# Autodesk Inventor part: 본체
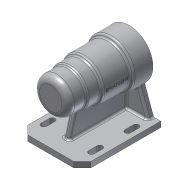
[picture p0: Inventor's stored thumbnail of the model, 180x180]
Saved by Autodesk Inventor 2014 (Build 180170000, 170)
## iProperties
Created: 2017-09
Part Number: 본체
Material: 알루미늄 6061
Document SubType Name: Modeling
Designer: user
Density: 2.71 g/cm^3
Appearance: 알루미늄 - 평지
Mass: 702.995 g
Surface Area: 713.313 cm^2
Volume: 259.408 cm^3
Author: user
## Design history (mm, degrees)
sketch "스케치1"
  geometry: L1 (0, 56)-(0, -56); L2 (0, 56)-(25, 56); L3 (25, 56)-(25, 31); L4 (25, 31)-(27, 31); L5 (27, 31)-(27, 11); L6 (27, 11)-(30, 11); L7 (30, 11)-(30, -28); L8 (30, -28)-(34, -28); L9 (34, -28)-(34, -56); L10 (34, -56)-(0, -56); 2 further points
  constraints: 20 end point, 6 parallel, 3 perpendicular, 1 coincident, 1 midpoint, 1 vertical
  dimensions: "d0" = 112 distance of L1.start L1.end; "d1" = 50 diameter of L3 L1; "d2" = 54 diameter of L5 L1; "d3" = 60 diameter of L7 L1; "d4" = 25 vertical distance of L2.end L4.end; "d5" = 45 distance between parallel lines of L6 L2; "d6" = 84 distance between parallel lines of L2 L8; "d7" = 112 distance between parallel lines of L2 L10 (derived); "d8" = 68 diameter of L9 L1
revolve "회전1" sketch "스케치1" stored, may be unused: angle "d9" = 90 deg
sketch "스케치2"
  geometry: C1 r 34 at (0, 0) reference; C2 r 21 at (0, 0)
  constraints: 1 centre point, 1 coincident
  dimensions: "d10" = 42 diameter of C2
extrude "돌출1" cut sketch "스케치2" distance "d11" = 15; taper "d12" = 0 deg
sketch "스케치3"
  geometry: C1 r 21 at (0, 0) reference; C2 r 24 at (0, 0)
  constraints: 1 centre point, 1 coincident
  dimensions: "d13" = 48 diameter of C2
extrude "돌출2" cut sketch "스케치3" distance "d14" = 54; taper "d15" = 0 deg
sketch "스케치4"
  geometry: C1 r 24 at (0, 0) reference; C2 r 21 at (0, 0)
  constraints: 1 centre point, 1 coincident
  dimensions: "d16" = 42 diameter of C2
extrude "돌출3" cut sketch "스케치4" distance "d17" = 12; taper "d18" = 0 deg
sketch "스케치5"
  geometry: C1 r 21 at (0, 0) reference; C2 r 17.5 at (0, 0)
  constraints: 1 centre point, 1 coincident
  dimensions: "d19" = 35 diameter of C2
extrude "돌출4" cut sketch "스케치5" distance "d20" = 18; taper "d21" = 0 deg
sketch "스케치6"
  geometry: C1 r 17.5 at (0, 0) reference; C2 r 16 at (0, 0)
  constraints: 1 centre point, 1 coincident
  dimensions: "d22" = 32 diameter of C2
extrude "돌출5" cut sketch "스케치6" distance "d23" = 4; taper "d24" = 0 deg
sketch "스케치7"
  geometry: C1 r 16 at (0, 0) reference; C2 r 10.5 at (0, 0)
  constraints: 1 centre point, 1 coincident
  dimensions: "d25" = 21 diameter of C2
extrude "돌출6" cut sketch "스케치7" distance "d26" = 3; taper "d27" = 0 deg
node "작업 평면1"
sketch "스케치8"
  geometry: L1 (-45, 56)-(45, 56); L2 (45, 56)-(45, -56); L3 (45, -56)-(-45, -56); L4 (-45, -56)-(-45, 56); L5 (-45, 56)-(45, -56); L6 (-45, -56)-(45, 56); 2 further points
  constraints: 12 end point, 2 parallel, 1 coincident, 1 horizontal, 1 midpoint, 1 perpendicular
  dimensions: "d29" = 90 distance of L2.end L3.end; "d30" = 112 distance of L1.end L2.end
extrude "돌출7" join sketch "스케치8" distance "d31" = 8; taper "d32" = 0 deg
sketch "스케치9"
  geometry: L1 (45, -62)-(-45, -62) reference; L2 (-21.9, -26.008)-(-35, -62); L3 (21.9, -26.008)-(35, -62); L4 (0, 0)-(0, -34); L5 (-35, -62)-(35, -62); A1 r 34 centre (0, 0) between (-21.9, -26.008) and (21.9, -26.008) reference; A2 r 34 centre (0, 0) between (-21.9, -26.008) and (21.9, -26.008)
  constraints: 8 end point, 6 point on circle, 2 point on line, 1 centre point, 1 collinear, 1 perpendicular
  dimensions: "d33" = 110 deg angle of L1 L3; "d34" = 110 deg angle of L1 L2; "d35" = 10 distance of L1.end L2.end; "d36" = 10 distance of L1.start L3.end
extrude "돌출8" join sketch "스케치9" distance "d37" = 8; taper "d38" = 0 deg
sketch "스케치10" dims "d39" = 52
  geometry: L1 (80, 8)-(90, 8) reference; L2 (45, 70)-(45, 96); A1 r 34 centre (45, 70) between (66.9, 43.992) and (23.1, 43.992) reference; 1 further point
  constraints: 2 coincident, 2 end point, 1 perpendicular, 1 vertical alignment, 2 other
hole "구멍1" sketch "스케치10" at (45, 96) diameter "d40" = 3.242; stored, may be unused: countersink angle "d44" = 90 deg, drill point angle "d46" = 118 deg; dims "d41" = 8, "d42" = 4, "d43" = 2, "d45" = 11
chamfer "모따기1" distance "d50" = 12; stored, may be unused: second distance "d51" = 2, angle "d52" = 45 deg
chamfer "모따기2" distance "d53" = 1; stored, may be unused: second distance "d54" = 2, angle "d55" = 45 deg
sketch "스케치11"
  geometry: L1 (-33, -56)-(33, -56) reference; L2 (-45, 56)-(45, 56) reference; L3 (0, -56)-(0, 56); L4 (-38, -20)-(-38, -32); L5 (-30, -32)-(-30, -20); L6 (-38, 32)-(-38, 20); L7 (-30, 20)-(-30, 32); L8 (30, -20)-(30, -32); L9 (38, -32)-(38, -20); L10 (30, 32)-(30, 20); L11 (38, 20)-(38, 32); A1 r 4 centre (-34, -32) between (-38, -32) and (-30, -32); A2 r 4 centre (-34, -20) between (-30, -20) and (-38, -20); A3 r 4 centre (-34, 32) between (-30, 32) and (-38, 32); A4 r 4 centre (-34, 20) between (-38, 20) and (-30, 20); A5 r 4 centre (34, -20) between (38, -20) and (30, -20); A6 r 4 centre (34, -32) between (30, -32) and (38, -32); A7 r 4 centre (34, 32) between (38, 32) and (30, 32); A8 r 4 centre (34, 20) between (30, 20) and (38, 20); 1 further point
  constraints: 18 end point, 16 point on circle, 12 tangent, 8 centre point, 5 vertical alignment, 2 midpoint
  dimensions: "d95" = 4 radius of A1; "d96" = 4 radius of A2; "d97" = 4 radius of A4; "d98" = 4 radius of A3; "d99" = 4 radius of A6; "d100" = 4 radius of A5; "d101" = 4 radius of A8; "d102" = 4 radius of A7; "d103" = 24 vertical distance of L2.end A7.centre; "d104" = 12 distance of A8.centre A7.centre; "d105" = 40 distance of A5.centre A8.centre; "d106" = 12 distance of A5.centre A6.centre; "d107" = 24 distance from line of L2 A3.centre; "d108" = 12 distance of A4.centre A3.centre; "d109" = 40 distance of A2.centre A4.centre; "d110" = 12 distance of A1.centre A2.centre; "d111" = 34 distance from line of L3 A1.centre; "d112" = 34 horizontal distance of L3.start A6.centre
extrude "돌출9" cut sketch "스케치11" stored distance "d75" = 8; taper "d76" = 0 deg
sketch "스케치12"
  geometry: L1 (-62, 44)-(-62, -56) reference; L2 (-62, 44)-(-62, 56) reference; L3 (-70, 44)-(-62, 44) reference; L4 (-70, -56)-(-70, 44) reference; L5 (-70, -56)-(-62, -56) reference; L6 (-62, 44)-(-62, -56) reference; L7 (-27, 31)-(-27, 11) reference; L8 (-30, 11)-(-30, -28) reference; L9 (-30, 11)-(30, 11) reference; L10 (-27, 31)-(27, 31) reference; L11 (-25, 56)-(-25, 31) reference; L12 (-27, 24.622)-(-62, 34); L13 (-62, 56)-(-70, 56) reference; 1 further point
  constraints: 2 end point, 2 point on line
  dimensions: "d77" = 105 deg angle of L1 L12; "d78" = 22 distance from line of L13 L12.end
feature "리브1" sketch "스케치12" dims "d79" = 1, "d80" = 8, "d81" = 0, "d82" = 0, "d83" = 1, "d84" = 1
fillet "모깎기1" dims "d85" = 3
fillet "모깎기2" dims "d86" = 3
fillet "모깎기3" dims "d87" = 9
fillet "모깎기4" dims "d88" = 3
fillet "모깎기5" dims "d89" = 3
fillet "모깎기6" dims "d90" = 0.3
node "작업 평면2"
sketch "스케치13"
  geometry: L1 (-24.711, -56)-(34, -56) reference; 2 further points
  constraints: 1 vertical alignment, 1 other
  dimensions: "d92" = 48 distance from line of L1 point (0, -8)
feature "엠보싱1" sketch "스케치13" dims "d93" = 0.5, "d94" = 0
node "솔리드1"
pattern_circular "원형 패턴1" dims angle "d48" = 360 deg
node "투영된 루프1"
other parameters: "d91" = 35
